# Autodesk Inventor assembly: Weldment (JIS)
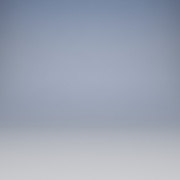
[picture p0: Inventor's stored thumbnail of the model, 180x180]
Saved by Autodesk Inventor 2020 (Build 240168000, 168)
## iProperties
Length Units: 11269
Angle Units: 11283
Time Units: 11279
Mass Units: 11290
Length Display Precision: 3
Angle Display Precision: 2
Part Number: Weldment (JIS)
Document SubType Name: Weldment
Created: 2002-06
Designer: smithga
Created: 2002-08
Designer: F.Stasiak
Weld Material: Welded Aluminum-6061
Manager: www.cadconsulting.pl
Company: Fabian Stasiak CAD Consulting
Control State: 0
Master: False
Shininess: 64.0
Angle Units: 11279
Time Units: 11290
Mass Units: 11283
Compacted: True
Density: 0.0
Volumn: 0.0
Area: 0.0
PropertySet Name: Model Information
Author: F.Stasiak
Subject: Zbiór ćwiczeń. Autodesk Inventor 2020. Kurs podstawowy
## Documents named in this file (1)
- M:\AUTOBUILD\M24_168_RTM\Application\App\Templates\en-US\Metric\Weldment (JIS).iam
